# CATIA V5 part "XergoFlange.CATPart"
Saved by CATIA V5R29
Part number: PoleMountFlange
Bounding box of the stored display mesh (mm): x -44 to 44, y -44 to 44, z -30 to 0
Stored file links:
  C:\Users\Administrator\Desktop\프로젝트\Boxfold\XergoFlange.CATPart
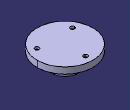
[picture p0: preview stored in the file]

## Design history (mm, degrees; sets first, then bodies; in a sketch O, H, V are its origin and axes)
Body1 (main body)
  Sketch1 on xy-plane, origin (0, 0, 0), H (1, 0, 0), V (0, -1, 0)
    circle A1 centre (0, 0) radius 44
    radius A1 = 44
  Pad1: profile Sketch1, direction (0, 0, -1), length 10
  Sketch2 on end face of Pad1, origin (0, 0, -10), H (1, 0, 0), V (0, -1, 0)
    circle A1 centre (0, 0) radius 20
    radius A1 = 20
  Pad2: profile Sketch2, direction (0, 0, -1), length 20
  Sketch3 on end face of Pad2, origin (0, 0, -30), H (1, 0, 0), V (0, -1, 0)
    circle A1 centre (0, 0) radius 15
    radius A1 = 15
  Pocket1: profile Sketch3, direction (0, 0, 1), up to end face of Pad1
  Sketch4 on yz-plane, origin (0, 0, 0), H (0, -1, 0), V (0, 0, -1)
    line L1 (20, 25) -> (40, 10)
    point P1 (20, 25)
    point P2 (40, 10)
    reference projected line E1 through (0, 0) direction (0, 1) from axis of face of Pad2 from Sketch2.A1
    reference projected line E2 through (0, 0) direction (0, 1) from axis of face of Pad1 from Sketch1.A1
    reference projected line E3 (-44, 10) -> (44, 10) from edge [face of Pad1 from Sketch1.A1 | end face of Pad1]
    reference projected line E4 (-20, 30) -> (20, 30) from edge [face of Pad2 from Sketch2.A1 | end face of Pad2]
    distance P1 E1 = 20
    distance P2 E2 = 40
    distance P1 E4 = 5
    coincidence: P2 E3
  Stiffener1: ExtendedProfile Sketch4, ThicknessTop 0, ThicknessValue 4
  CircPattern1: of Stiffener1, instances 3, angular step 120 {= 360.0*1 deg/CircPattern1.AngularNumber}, axis from Z axis
  Fillet1: radius 3, on edge [face of CircPattern1 | end face of Pad1] (x4); edge [end face of Pad1 | face of Pad2 from Sketch2.A1] (x3); edge [face of Stiffener1 | end face of Pad1] (x2); edge [face of CircPattern1 | face of Pad2 from Sketch2.A1] (x2); edge [face of Pad2 from Sketch2.A1 | face of Stiffener1] (x2); edge [face of Stiffener1 | face of Pad2 from Sketch2.A1]; edge [face of Pad2 from Sketch2.A1 | face of CircPattern1] (x4)
  Sketch5 on end face of Pad1, origin (0, 0, -10), H (1, 0, 0), V (0, -1, 0)
    point P1 (-28.1458, 16.25)
    construction line L1 (0, 0) -> (-28.1458, 16.25)
    construction circle A1 centre (0, 0) radius 32.5
    angle L1 H = 150
    radius A1 = 32.5
    coincidence: A1 P1
  Hole1: placed by Sketch5, at (-28.1458, -16.25, -10) direction (0, 0, 1), diameter 6.6, through (limit type 3), counterbore diameter 11, counterbore depth 6.5
  CircPattern2: of Hole1, instances 3, angular step 120, axis from Z axis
